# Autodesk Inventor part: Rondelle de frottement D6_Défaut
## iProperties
Shininess: 64.0
Length Units: 11269
Angle Units: 11279
Time Units: 11290
Mass Units: 11283
Length Display Precision: 3
Angle Display Precision: 2
Compacted: True
Part Number: Rondelle de frottement D6_Défaut
Document SubType Name: Modeling
Created: 2006-01
Material: Par défaut
Designer: Fricot
Density: 0.0
Volumn: 0.0
Area: 0.0
PropertySet Name: Model Information
Control State: 0
Master: False
Checked Out: False
Author: Fricot
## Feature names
1. Base1
